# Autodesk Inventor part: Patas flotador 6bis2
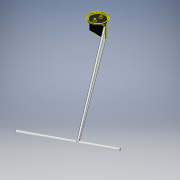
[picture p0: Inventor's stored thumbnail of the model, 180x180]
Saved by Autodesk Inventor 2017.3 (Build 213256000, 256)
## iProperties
Part Number: Patas flotador 6bis2
Material: Plástico ABS
Document SubType Name: Modeling
Designer: PABLO HERNANDEZ
Density: 1.06 g/cm^3
Appearance: Suave - Blanco
Mass: 4.28877 g
Surface Area: 39.5254 cm^2
Volume: 4.04601 cm^3
Author: M.RICO
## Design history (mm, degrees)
sketch "Boceto1"
  geometry: C1 r 16 at (0, 0); 1 further point
  constraints: 1 centre point, 1 coincident
  dimensions: "d0" = 32 diameter of C1
extrude "Extrusión1" new body sketch "Boceto1" distance "d1" = 1; taper "d2" = 0 deg; dims "d93" = 1, "d94" = 0
sketch "Boceto2"
  geometry: C1 r 16 at (0, 0); C2 r 15 at (0, 0); C3 r 14 at (0, 0); 1 further point
  constraints: 3 centre point, 1 coincident
  dimensions: "d3" = 1 radial gap between concentric circles of C1 C2; "d4" = 1 radial gap between concentric circles of C2 C3
extrude "Extrusión2" join sketch "Boceto2" distance "d5" = 3; taper "d6" = 0 deg
sketch "Boceto3"
  geometry: C1 r 15 at (0, 0); C2 r 14 at (0, 0); 1 further point
  constraints: 2 centre point, 1 coincident
  dimensions: "d7" = 1 radial gap between concentric circles of C1 C2; "d123" = 30 diameter of C1
extrude "Extrusión3" join sketch "Boceto3" distance "d8" = 2; taper "d9" = 0 deg
sketch "Boceto4"
  geometry: C1 r 16 at (0, 0); 1 further point
  constraints: 1 centre point, 1 coincident
extrude "Extrusión4" cut sketch "Boceto4" distance "d10" = 0.5; taper "d11" = 0 deg
sketch "Boceto7"
  geometry: L1 (1.5, -15.93)-(1.5, 15.93); L2 (-1.5, -15.93)-(-1.5, 15.93); A1 r 16 centre (0, 0) between (1.5, 15.93) and (-1.5, 15.93); A2 r 16 centre (0, 0) between (-1.5, -15.93) and (1.5, -15.93); 2 further points
  constraints: 4 end point, 4 point on circle, 2 centre point, 1 coincident
extrude "Extrusión7" join sketch "Boceto7" distance "d63" = 25; taper "d64" = 0 deg
fillet "Empalme2" dims "d95" = 3
fillet "Empalme3" dims "d96" = 0.5
sketch "Boceto13"
  geometry: C1 r 1.2 at (-6, 0) reference; C2 r 1.75 at (-6, 0); C3 r 1.2 at (6, 0) reference; C4 r 1.75 at (6, 0); 1 further point
  constraints: 2 centre point, 2 coincident
  dimensions: "d118" = 3.5 diameter of C2; "d119" = 3.5 diameter of C4
extrude "Extrusión10" join sketch "Boceto13" distance "d120" = 3; taper "d121" = 0 deg
fillet "Empalme4" dims "d122" = 1
sketch "Boceto14"
  geometry: 1 further point
sketch "Boceto15"
  geometry: C1 r 1.2 at (6, 0) reference; C2 r 2.5 at (6, 0); C3 r 1.2 at (-6, 0) reference; C4 r 2.5 at (-6, 0); 1 further point
  constraints: 2 centre point, 2 coincident
  dimensions: "d124" = 5 diameter of C2; "d125" = 5 diameter of C4
extrude "Extrusión11" cut sketch "Boceto15" distance "d126" = 10; taper "d127" = 0 deg
hole "Agujero7" diameter "d151" = 2.4; stored, may be unused: countersink angle "d155" = 90 deg, drill point angle "d157" = 118 deg; dims "d149" = 10, "d150" = 10, "d152" = 6, "d153" = 4, "d154" = 2, "d156" = 8
hole "Agujero8" diameter "d160" = 2.4; stored, may be unused: countersink angle "d164" = 90 deg, drill point angle "d166" = 118 deg; dims "d158" = 10, "d159" = 10, "d161" = 6, "d162" = 4, "d163" = 2, "d165" = 8
node "Eje de trabajo1"
feature "Desplazar cuerpo1"
feature "Compuesta1"
feature "Desplazar cuerpo2"
node "Eje de trabajo2"
feature "Desplazar cuerpo3"
node "Plano de trabajo6"
sketch "Boceto27"
  geometry: L1 (0, 0)-(-149.324, -102.291); L2 (-134.431, -229.557)-(132.044, -87.232); C1 r 14 at (-149.324, -102.291) reference
  constraints: 4 end point
node "Plano de trabajo7"
node "Plano de trabajo8"
sketch "Boceto28"
  geometry: C1 r 2 at (0, 0); 1 further point
  constraints: 1 centre point
  dimensions: "d177" = 4 diameter of C1
extrude "Extrusión14" join sketch "Boceto28" stored distance "d178" = 10; taper "d179" = 0 deg
sketch "Boceto29"
  geometry: L1 (-0.28, 0)-(0, 0) reference; L2 (0, 0)-(-102.216, -91.987); L3 (-0.28, 23.165)-(-0.28, 0) reference; L4 (0, 23.165)-(0, 0) reference; L5 (0, 0)-(0, 23.165); L6 (0, 23.165)-(-105.015, -89.134); C1 r 2 at (-103.554, -90.5) reference; A1 r 2 centre (-103.554, -90.5) between (-102.216, -91.987) and (-105.015, -89.134) reference; 1 further point
  constraints: 6 end point, 2 point on circle, 2 tangent, 1 collinear
extrude "Extrusión15" join sketch "Boceto29" stored distance "d180" = 10; taper "d181" = 0 deg
node "Plano de trabajo9"
sketch "Boceto30"
  geometry: L1 (1.356, 23.165)-(1.356, 0) reference; L2 (1.356, 0)-(-130.469, -92.139); L3 (1.356, 0)-(1.356, 23.165); L4 (1.356, 23.165)-(-132.897, -88.965); A1 r 2 centre (-131.615, -90.5) between (-130.469, -92.139) and (-132.897, -88.965) reference; A2 r 2 centre (-131.615, -90.5) between (-132.897, -88.965) and (-130.469, -92.139); 1 further point
  constraints: 6 end point, 4 point on circle, 2 tangent, 1 centre point, 1 coincident, 1 vertical
extrude "Extrusión16" join sketch "Boceto30" distance "d182" = 3; taper "d183" = 0 deg
node "Plano de trabajo10"
sketch "Boceto31"
  geometry: L1 (-7.175, -6.405)-(170.651, -6.405); L2 (170.651, -6.405)-(170.651, 129.955); L3 (170.651, 129.955)-(-7.175, 129.955); L4 (-7.175, 129.955)-(-7.175, -6.405); 1 further point
  constraints: 8 end point, 2 parallel, 1 horizontal, 1 perpendicular
extrude "Extrusión17" cut sketch "Boceto31" distance "d185" = 150; taper "d186" = 0 deg
sketch "Boceto32"
  geometry: C1 r 1 at (0, 0); 1 further point
  constraints: 1 centre point
  dimensions: "d187" = 2 diameter of C1
extrude "Extrusión18" cut sketch "Boceto32" distance "d188" = 6; taper "d189" = 0 deg
sketch "Boceto33"
  geometry: L1 (31.859, 0)-(0, 0) reference; L2 (0, -3)-(31.859, -3) reference; L3 (31.859, 0)-(0, 0); L4 (0, 0)-(0, -3); L5 (0, -3)-(31.859, -3); L6 (31.859, -3)-(31.859, 0); 1 further point
  constraints: 8 end point, 2 parallel, 1 horizontal, 1 perpendicular
extrude "Extrusión19" cut sketch "Boceto33" distance "d191" = 24; taper "d192" = 0 deg
node "Sólido1"
node "Sup1"
other parameters: "sa_0" = 4, "d167" = 90 deg, "d168" = -149.324, "d169" = -102.291, "d170" = 0, "d171" = 9.86699, "d184" = 147
